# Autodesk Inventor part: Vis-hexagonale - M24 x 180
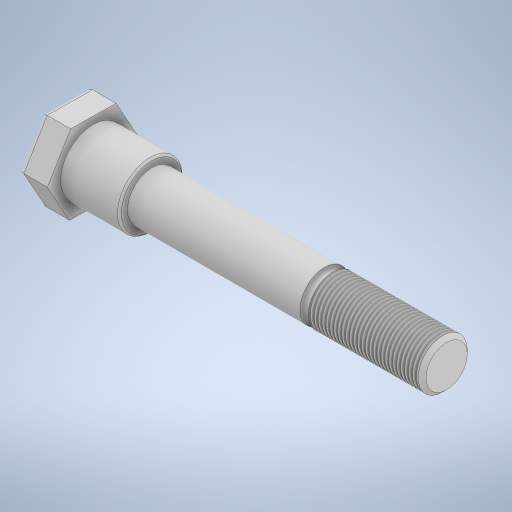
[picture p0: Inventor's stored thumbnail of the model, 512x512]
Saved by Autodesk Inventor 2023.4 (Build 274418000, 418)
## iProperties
Created: 2025-03
Part Number: Vis-hexagonale - M24 x 180
Material: Générique
Document SubType Name: Modeling
Designer: bruno
Density: 1 g/cm^3
Appearance: Par défaut
Author: bruno
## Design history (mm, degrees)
sketch "Esquisse1"
  geometry: L1 (-20.162, -11.262)-(-19.834, 11.829); L2 (-19.834, 11.829)-(0.327, 23.092); L3 (0.327, 23.092)-(20.162, 11.262); L4 (20.162, 11.262)-(19.834, -11.829); L5 (19.834, -11.829)-(-0.327, -23.092); L6 (-0.327, -23.092)-(-20.162, -11.262); 2 further points
  constraints: 12 end point, 1 coincident, 13 other
  dimensions: "d0" = 40 distance between parallel lines of L1 L4
extrude "Extrusion1" new body sketch "Esquisse1" distance "d1" = 14; taper "d2" = 0 deg
sketch "Esquisse2"
  geometry: C1 r 12.5 at (0, 0); 1 further point
  constraints: 1 centre point, 1 coincident
  dimensions: "d3" = 25 diameter of C1
extrude "Extrusion2" join sketch "Esquisse2" distance "d4" = 180; taper "d5" = 0 deg
chamfer "Chanfrein1" distance "d6" = 2; stored, may be unused: second distance "d7" = 2, angle "d8" = 45 deg
sketch "Esquisse3"
  geometry: L1 (14, 12.5)-(192, 12.5) reference; L2 (194, 10.5)-(194, -10.5) reference; L3 (0, -15.511)-(0, 19.565) reference; L4 (-38.8, 0)-(232.8, 0) reference; L5 (14, 12.5)-(44, 12.5); L6 (44, 12.5)-(44, 14.324); L7 (44, 14.324)-(14, 14.324); L8 (14, 14.324)-(14, 12.5); C1 r 2.054 at (134, 12.5); 3 further points
  constraints: 8 end point, 2 parallel, 1 centre point, 1 horizontal, 1 perpendicular, 1 point on line
  dimensions: "d9" = 60 distance from line of L2 C1.centre; "d13" = 30 distance of L7.end L6.end
revolve "Révolution1" sketch "Esquisse3" stored, may be unused: angle "d10" = 360 deg
feature "Filetage1" dims "d11" = 55.946, "d12" = 0
sketch "Esquisse4"
  geometry: L1 (14, 20.162)-(14, 0.327) reference; L2 (14, 12.5)-(14, -12.5) reference; L3 (131.946, 12.5)-(131.946, -12.5) reference; L4 (14, 12.5)-(44, 12.5); L5 (44, 12.5)-(44, 16.5); L6 (44, 16.5)-(14, 16.5); L7 (14, 16.5)-(14, 12.5); L8 (-26.389, 0)-(158.335, 0) reference; 3 further points
  constraints: 8 end point, 2 parallel, 1 horizontal, 1 perpendicular
  dimensions: "d14" = 30 distance of L6.end L5.end; "d15" = 4 distance of L5.end L4.end
revolve "Révolution2" sketch "Esquisse4" stored, may be unused: angle "d16" = 90 deg
fillet "Congé1" dims "d17" = 2
chamfer "Chanfrein2" distance "d18" = 1; stored, may be unused: second distance "d19" = 2, angle "d20" = 45 deg
node "Solide1"
node "Boucle projetée1"
